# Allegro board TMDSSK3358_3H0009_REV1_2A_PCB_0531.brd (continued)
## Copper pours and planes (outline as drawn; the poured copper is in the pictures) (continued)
VBAT on BOTTOM: 116.71,26.8 117.47,27.56 117.47,32.51 117.86,32.89 122.17,32.89 122.55,32.51 122.55,27.94 117.86,23.24 117.86,21.46 116.08,19.69 107.7,19.69 106.55,20.83 106.55,22.48 107.67,23.6 107.67,24.65 109.82,26.8
VBAT on BOTTOM: 29.93,28.02 29.93,25.1 29.8,24.97 29.8,23.83 29.93,23.7 31.32,23.7 31.45,23.83 31.45,24.71 30.94,25.22 30.94,27.89 30.82,28.02
VBAT on BOTTOM: 120.34,46.36 123.7,46.36 123.83,46.23 123.83,44.7 123.63,44.51 122.62,44.51 122.39,44.29 122.39,43.33 122.24,43.18 120.35,43.18 120.03,43.51 120.03,46.05
VBAT on LYR4_PWR1: 87.9,0.94 87.9,4.87 87.62,5.15 61.13,5.15 60.97,5 60.97,1.21 61.46,0.73 87.69,0.73
VBAT on LY5_PWR2: 8.16,1.34 8.16,3.76 7.9,5.22 7.15,6.5 21.71,6.5 24.63,9.42 24.63,17.55 22.87,19.3 0.89,19.3 0.89,53.53 1.39,54.02 30.42,54.02 31.26,53.18 31.26,31.56 44.07,18.74 56.63,18.74 57.07,18.3 57.07,16.26 58.79,14.55 58.79,10.44 64.02,5.2 81.66,5.2 86.59,10.13 108.74,10.13 111.31,12.7 111.31,27.08 110.65,27.73 109.06,27.73 108.75,28.04 108.75,41.51 110.87,43.63 112.69,43.63 113.85,44.79 113.85,46.55 113.28,47.12 106.51,47.12 106.03,47.6 106.03,51.48 106.24,51.69 107.31,51.69 107.35,51.72 116.84,51.72 119.39,49.17 123.28,49.17 124.7,50.59 124.7,62.61 125.14,63.04 132.28,63.04 132.64,62.68 132.64,8.39 132.22,7.97 127.78,7.97 124.8,6.73 123.56,3.76 123.56,1.12 123.33,0.89 8.62,0.89
VBAT_WLAN on TOP: 20.28,32.97 20.28,36.91 20.91,36.91 21.04,37.03 21.04,38.43 20.94,38.52 20.94,39.22 19.95,40.21 19.64,40.21 19.13,39.7 19.13,36.52 18.37,35.76 18.37,33.22 18.62,32.97
VBAT_WLAN on BOTTOM: 19.3,40.51 19.3,38.73 20.07,37.97 24.64,37.97 25.27,38.61 25.27,40.51 25.02,40.77 19.56,40.77
VBAT_WLAN_OUT on BOTTOM: 19.64,45.03 19.5,45.03 19.5,43.4 19.77,43.13 19.77,41.73 20.02,41.48 24.97,41.48 25.1,41.61 25.1,43 23.45,44.65 20.02,44.65
VDD_1V8FT on TOP: 30.66,31.75 30.66,25.91 32.7,23.88 36,23.88 38.67,26.54 39.68,26.54 41.87,28.73 43.97,28.73 45.9,26.8 48.52,26.8 49.66,25.65 50.55,25.65 50.98,26.09 50.98,28.19 46.29,32.89 31.81,32.89
VDD_CORE on TOP: 104.22,41.18 103.46,41.18 102.84,40.55 102.84,39.19 104.01,38.02 106.43,38.02 106.76,38.35 108.39,38.35 108.59,38.56 108.59,39.65 108.44,39.8 107.55,39.8 106.91,40.44 106.91,41.99 106.51,42.39 104.68,42.39 104.37,42.09 104.37,41.33
VDD_CORE on TOP: 71.94,29.72 76.26,29.72 76.89,30.35 76.89,33.4 73.84,36.45 71.09,36.45 70.78,36.14 70.78,35.6 70.25,35.06 70.25,31.41
VDD_CORE on BOTTOM: 108.77,40 108.77,40.36 107.88,41.25 107.11,41.25 106.2,42.16 104.86,42.16 104.45,41.76 104.45,41.38 104.12,41.05 103.28,41.05 102.93,40.69 102.93,38.43 103.26,38.1 108.13,38.1 108.41,38.38 108.41,38.76 109.09,39.45 109.12,39.45 109.26,39.59 110.38,39.59 110.54,39.75 111.34,39.75 111.34,39.92 109.66,39.92 109.58,40
VDD_CORE on LYR4_PWR1: 64.33,32.43 64.33,39.59 69.82,45.08 91.62,45.08 93.36,43.35 107.07,43.35 108.13,42.29 108.13,38.09 108.02,37.97 74.1,37.97 73.59,37.47 73.59,36.05 74.16,35.48 74.69,35.48 75.35,34.82 75.35,34.26 76.71,32.9 76.71,31.95 76.51,31.75 65.01,31.75
VDD_FTREGIN on BOTTOM: 36.86,37.41 36.86,35.94 37.31,35.48 37.31,34.24 37.54,34.24 37.54,35.53 38.13,36.12 38.13,37.41
VDD_MPU on BOTTOM: 112.41,30.81 113.42,31.81 113.42,32.46 113.72,32.77 114.61,32.77 114.85,32.52 114.85,31.41 115.08,31.19 115.08,29.66 113.12,27.71 105.17,27.71 105.04,27.84 105.04,30.04 105.3,30.3 106.94,30.3 107.46,30.81
VDD_MPU_AM335X on TOP: 89.42,30.42 89.42,31.13 89.66,31.37 91.06,31.37 91.31,31.11 91.31,30.03 90.55,29.27 90.55,27.69 90.3,27.43 89.15,27.43 88.65,27.94 88.65,29.64
VDD_MPU_AM335X on BOTTOM: 106.86,33.53 103.44,33.53 103.14,33.23 103.14,32.08 100.72,29.66 100.72,28.52 101.49,27.76 104.41,27.76 104.66,28.01 104.66,29.66 104.41,29.92 104.41,30.81 104.66,31.06 106.81,31.06 107.12,31.37 107.12,33.27
VDD_MPU_AM335X on LYR4_PWR1: 87.69,27.78 105.25,27.78 108.13,30.67 108.13,37.19 107.98,37.34 74.33,37.34 74.1,37.11 74.1,36.1 74.33,35.86 74.84,35.86 75.73,34.97 75.73,34.46 77.09,33.1 77.09,32.11 77.62,31.57 83.91,31.57
VDDA_ADC on TOP (solid shape): outline of 156 points within 79.43,30.12 85.1,32.51
VDDL_PHY on BOTTOM: 92.1,41.17 91.55,41.17 91.32,40.94 88.9,40.94 88.87,40.97 88.87,41.5 89.03,41.66 89.03,42.88 88.77,43.13 88.77,45.4 88.5,45.67 88.25,45.67 87.94,45.97 87.94,47.88 88.7,48.64 92.13,48.64 92.23,48.54 92.23,46.71 92.23,46.71 90.65,45.14 90.65,44.07 91.59,43.13 91.77,43.13 92.24,42.66 92.24,41.31
VDDL_PHY2 on BOTTOM: 49.33,41.15 48.93,41.55 48.93,42.14 48.39,42.68 48.39,44.42 47.37,45.44 47.37,49.91 47.62,50.17 51.82,50.17 52.2,49.78 52.2,48.77 51.94,48.51 49.28,48.51 48.89,48.13 48.89,46.29 49.51,45.67 49.51,43.33 50.7,42.14 51.39,42.14 51.9,41.63 51.9,41.48 51.57,41.15
VDDS_DDR on BOTTOM: 126.36,34.04 119.92,34.04 119.83,34.13 119.83,34.36 120.05,34.59 120.31,34.59 120.64,34.92 120.64,35.2 120.82,35.38 121.81,35.38 122.44,36.01 122.44,37.38 122.1,37.72 121.88,37.72 121.62,37.97 121.62,38.93 120.64,39.92 120.64,39.92 120.41,40.15 119.04,40.15 118.89,40 118.45,40 118.02,40.43 118.02,40.56 118.48,40.56 118.91,40.99 120.84,40.99 122.08,39.75 127.25,39.75 127.63,39.37 127.63,37.34 127.13,36.83 127.13,34.8
VDDS_DDR on BOTTOM: 63.26,13.15 63.4,13.29 63.4,15.13 63.27,15.27 61.43,15.27 60.85,14.68 59.2,14.68 58.94,14.42 58.94,12.39 59.83,11.5 60.69,11.5 62.35,13.15
VDDS_DDR on LYR4_PWR1: 87.65,5.71 61.17,5.71 60.97,5.91 60.97,8.86 59.4,10.43 59.4,15.24 59.98,15.82 59.98,22.88 60.11,23.01 63.36,23.01 68.36,28.01 69.74,28.01 70.24,28.51 70.24,30.92 70.43,31.11 78.14,31.11 78.16,31.09 81.22,31.09 81.82,31.69 84.01,31.69 83.96,31.75 84.24,31.75 88.43,27.55 105.42,27.55 108.88,31.01 108.88,38.48 109.14,38.73 122.94,38.73 123.7,37.97 123.7,34.16 120.2,30.66 120.2,20.58 118.67,19.05 91.26,19.05 87.91,15.7 87.91,5.98
VDDS_DDR on LY5_PWR2: 61.51,15.21 61.74,15.44 61.74,19.38 67.91,25.55 76.65,25.55 78.32,27.22 78.32,27.91 78.42,28.01 82.66,28.01 88.45,22.23 93.68,22.23 93.99,21.92 93.99,11.68 93.08,10.77 86.36,10.77 81.33,5.74 67.25,5.74 67.2,5.69 63.59,5.69 59.35,9.93 59.35,14.75 59.81,15.21
VDDS_DDR3_AM335X on TOP: 74.99,28.57 74.86,28.7 74.23,28.7 74.1,28.57 72.14,28.57 72.12,28.6 72.12,29.13 72.04,29.21 71.56,29.21 71.51,29.26 71.51,29.51 71.53,29.54 72.42,29.54 72.55,29.41 73.79,29.41 73.84,29.46 75.7,29.46 75.83,29.34 76.86,29.34 77.07,29.54 77.07,29.9 77.11,29.94 77.11,29.95 77.4,29.95 77.45,29.9 77.45,28.6 77.45,28.6 77.45,26.9 77.34,26.8 75.44,26.8 74.99,27.25
VDDS_DDR3_AM335X on BOTTOM: 59.31,18.8 59.56,19.05 59.56,23.24 59.69,23.37 60.82,23.37 61.13,23.06 61.13,22.3 61.98,21.45 61.98,20.8 62.48,20.29 62.48,18.35 61.35,17.22 61.35,15.95 60.85,15.44 59.2,15.44 58.94,15.69 58.94,17.6 59.31,17.97
VDDS_DDR3_AM335X on LY5_PWR2: 58.5,15.57 60.95,15.57 61.1,15.72 61.1,19.5 67.53,25.93 76.46,25.93 77.95,27.42 77.95,29.11 77.83,29.23 64.88,29.23 64.72,29.07 64.72,27.28 64.43,26.99 64.43,26.15 63.52,25.24 62.68,25.24 57.72,20.28 57.72,16.34
VDDSHV1 on TOP (solid shape): outline of 842 points within 58.67,26.16 69.85,50.31
VDDSHV2 on TOP: 66.15,33.35 69.15,33.35 69.37,33.58 69.65,33.58 69.85,33.78 69.85,34.62 69.55,34.92 68.38,34.92 67.8,35.51 67.8,36.77 67.07,37.5 67.07,38.55 65.42,40.2 65.42,43.63 64.4,44.65 64.4,46.68 63.26,46.68 63.13,46.55 63.13,44.67 64.28,43.53 64.28,39.41 66.05,37.64 66.05,33.45
VDDSHV2 on BOTTOM: 66.17,44.6 66.17,43.23 65.81,42.87 64.06,42.87 63.75,43.18 63.75,45.36 64.42,46.02 65.94,46.02 66.05,45.91 66.05,44.72
VDDSHV3 on TOP: 70.99,43.43 69.98,42.42 69.98,37.87 70.24,37.61 70.24,35.57 69.85,35.18 68.76,35.18 68.15,35.79 68.15,36.59 68.97,37.41 68.97,38.93 68.72,39.19 68.72,41.85 68.58,41.85 68.58,42.8 69.15,43.36 69.15,47.45 69.95,48.26 70.69,48.26 70.99,47.96
VDDSHV4 on TOP: 75.56,41.38 75.56,39.39 74.17,37.99 74.17,36.83 74.42,36.58 75.56,36.58 75.69,36.7 75.69,36.34 76.83,37.48 76.83,37.54 77.74,38.44 77.74,39.7 77.1,40.33 77.1,40.46 78.25,41.6 78.88,41.6 80.02,42.74 80.02,46.68 80.79,47.44 80.79,47.64 80.76,47.67 80.76,49.63 79.77,50.62 77.23,50.62 76.98,50.36 76.98,49.73 78.25,48.46 78.25,43.1 76.19,43.1 75.91,42.83 75.91,41.73
VDDSHV4 on LY3_SIG1: 98.71,62.08 102.17,65.53 108.26,65.53 108.77,66.04 108.77,68.71 108.39,69.09 96.27,69.09 95.56,68.38 95.56,62.78 96.27,62.08
VDDSHV5 on TOP: 71.37,46.99 71.37,43.31 70.99,42.93 70.99,37.19 71.39,36.79 72.94,36.79 73.15,37.01 73.15,37.39 73.46,37.7 73.46,40.67 73.15,40.98 73.15,47.09 72.97,47.27 71.65,47.27
VDDSHV6 on TOP: 80.96,45.08 84.26,45.08 84.39,44.96 84.39,42.98 84.2,42.8 81.08,42.8 80.83,43.05 80.83,44.96
VDDSHV6 on BOTTOM: 32,44.83 32,43.69 32.38,43.31 48.06,43.31 48.19,43.43 48.19,44.07 48.06,44.2 47.56,44.2 46.54,45.21 32.38,45.21
VDDSHV6 on LYR4_PWR1: 66.89,26.63 67.61,27.35 67.61,27.53 67.82,27.75 68,27.75 68.24,27.99 68.24,28.13 68.46,28.35 69.39,28.35 69.72,28.68 69.74,28.66 69.74,30.97 69.6,31.11 65.95,31.11 65.93,31.1 64.75,31.1 59.83,26.18 59.83,23.64 60.16,23.31 63.59,23.31 66.89,26.61
VDDSHV6 on LY5_PWR2: 44.49,19.17 31.66,32 31.66,53.28 30.39,54.55 1.37,54.55 0.89,55.04 0.89,62.68 1.25,63.04 3.95,63.04 6.93,64.28 8.16,67.25 8.16,69 9.28,70.12 34.51,70.12 34.52,70.13 45.39,70.13 45.59,69.92 45.59,48.92 47.55,46.96 47.55,38.91 48.44,38.02 51.36,38.02 52.63,39.29 52.63,52.35 59.97,59.69 97.51,59.69 97.92,59.28 97.92,53.47 99.72,51.66 105.19,51.66 105.41,51.44 105.41,46.76 104.1,45.44 104.1,45.41 101.77,43.08 101.77,33.75 103.8,31.72 103.8,30.51 101.7,28.42 91.38,28.42 87.01,32.79 87.01,35.4 85.69,36.72 84.62,36.72 81.98,34.08 77.76,34.08 75.5,36.35 75.5,37.21 75.75,37.47 76.26,37.47 77.15,36.58 77.67,36.58 77.89,36.8 77.89,37.74 78.25,38.1 82.1,38.1 82.11,38.11 84.25,38.11 86.26,40.13 86.26,41.35 85.07,42.55 68.51,42.55 64.32,38.35 64.32,27.29 57.54,20.52 57.54,19.99 56.73,19.17
VDDSHV6 on LY6_SIG2: 75.73,36.75 75.85,36.64 76.05,36.64 76.33,36.36 76.33,34.48 77.23,33.57 77.51,33.57 77.74,33.8 77.74,36.37 76.87,37.23 75.81,37.23 75.73,37.16
(no net) on TOP: 79.53,31.78 79.43,31.88 79.43,32.39 79.56,32.51 83.02,32.51 83.33,32.2 84.62,32.2 85.1,31.72 85.1,30.28 84.94,30.12 82.35,30.12 80.7,31.78
(no net) on TOP: 23.58,49.38 22.29,49.38 22.05,49.61 22.05,50.88 22.31,51.13 25.48,51.13 25.86,50.75 25.86,49.86 25.61,49.61 23.81,49.61
(no net) on TOP: 65.02,32.77 69.3,32.77 69.6,32.51 69.85,32.26 69.85,31.29 69.55,30.99 65.34,30.99 63.81,29.46 63.15,28.8 61.31,28.8 60.71,28.19 60.71,26.29 60.58,26.16 58.76,26.16 58.67,26.25 58.67,29.84 58.8,29.97 60.89,29.97 63.08,32.17 63.08,35.02 63.12,35.05 63.12,35.38 62.2,36.3 62.2,36.65 61.74,37.12 61.74,38.41 62.2,38.88 62.2,42.66 61.48,43.38 61.48,46.83 62.78,48.12 62.78,48.87 64.22,50.31 67.4,50.31 67.65,50.06 67.65,49.75 66.82,48.92 65.82,48.92 64.5,47.6 63.41,47.6 62.75,46.93 62.75,44.27 63.88,43.14 63.88,38.99 63.5,38.61 63.5,37.34 63.88,36.96 63.88,36.45 64.39,35.94 64.39,34.8 63.88,34.29 63.88,33.91
(no net) on BOTTOM: 27.32,50.55 25.74,48.97 22.89,48.97 22.85,49.02 22.85,49.22 23.47,49.84 23.67,49.84 25.06,51.23 25.06,52.04 25.43,52.4 28.08,52.4 28.23,52.25 28.23,50.65 28.12,50.55
(no net) on BOTTOM: 27.3,46.39 25.23,48.46 22.92,48.46 22.82,48.37 22.76,48.37 22.76,47.75 22.92,47.6 23.68,47.6 25.46,45.82 25.46,44.71 25.64,44.53 28.04,44.53 28.2,44.68 28.2,46.26 28.07,46.39
(no net) on BOTTOM: 22.05,51.84 22.23,52.02 23.7,52.02 23.83,51.89 23.83,50.59 23.46,50.21 23,50.21 22.54,49.75 22.54,49.5 22.47,49.42 21.88,49.42 21.88,49.78 22.05,49.95
BKLT_L on BOTTOM: 26.37,41.86 26.37,40.08 25.99,39.7 25.99,35.51 26.5,35 28.02,35 28.28,35.26 28.28,41.48 27.64,42.11 26.63,42.11
BKLT_SW on BOTTOM: 29.29,41.99 29.29,35.18 29.47,35 30.57,35 31.83,36.26 31.83,39.83 30.56,41.1 30.56,42.11 30.31,42.37 29.67,42.37
CHASSIS_ETH1 on TOP: 78.1,58.04 89.79,58.04 91.57,59.82 93.85,59.82 94.11,59.56 94.11,55.75 93.54,55.18 92.01,55.18 90.93,56.26 79.5,56.26 79.44,56.2 78.68,56.2 77.85,55.37 75.31,55.37 74.68,56.01 74.68,58.93 75.31,59.56 76.58,59.56
CHASSIS_ETH2 on TOP: 53.04,58.17 53.04,55.22 54.08,54.18 55.8,54.18 56.87,55.25 70.69,55.25 70.97,55.52 71.81,55.52 73.25,56.97 73.25,58.04 72.92,58.37 72.14,58.37 71.55,58.95 70.23,58.95 68.99,57.71 67.18,57.71 67.23,57.76 56.21,57.76 54.89,59.08 53.95,59.08
CHASSIS_SD on BOTTOM: 100.76,54.89 100.13,55.52 100.13,56.08 99.23,56.98 99.23,57.68 99.05,57.86 98.41,57.86 98.34,57.78 98.34,57.05 98.08,56.79 97.05,56.79 96.44,57.4 96.44,60.76 97.41,61.72 97.41,62.89 97.18,63.12 96.34,63.12 94.01,65.46 94.01,69.65 94.73,70.37 98.53,70.37 98.53,69.14 98.25,68.86 96.44,68.86 96.09,68.5 96.09,66.45 96.9,65.63 98.25,65.63 98.97,64.91 99.23,64.91 99.82,64.31 110.54,64.31 113.03,66.8 113.03,68.53 112.67,68.88 111.46,68.88 111.4,68.94 111.4,70.2 111.58,70.37 115.3,70.37 115.95,69.72 115.95,66.98 115.34,66.37 115.34,66.32 115.14,66.12 114.53,66.12 114.35,65.94 114.35,65.46 113.49,64.59 113.49,59.33 110.57,56.41 110.59,56.41 109.07,54.89
CHASSIS_USB0 on LY3_SIG1: 49.87,69.42 49.87,66.75 48.52,65.41 37.5,65.41 35.9,67.01 35.9,69.55 36.28,69.93 49.36,69.93
CHASSIS_USB1 on TOP: 28.91,65.23 31.71,65.23 33.36,63.58 33.36,60.15 31.96,58.75 29.29,58.75 27.9,60.15 27.9,64.21
CHASSIS_USB1 on LY6_SIG2: 27.9,59.26 19.79,59.26 18.47,57.94 15.5,57.94 14.28,59.16 14.28,66.62 15.98,68.33 29.7,68.33 33.28,64.74 33.28,58.72 32.37,57.81 29.34,57.81
LED+ on TOP: 31.37,34.79 29.27,34.79 28.15,35.92 28.15,37.29 28.55,37.69 29.48,37.69 30.33,38.54 30.33,40.39 30.49,40.56 31.69,40.56 31.81,40.43 31.81,38.78 30.54,37.51 30.54,35.96 30.65,35.86 30.9,35.86 31.37,35.39
LED- on TOP: 31.31,34.49 31.46,34.34 31.46,33.14 31.34,33.02 28.84,33.02 27.8,34.06 26.68,34.06 25.99,34.75 25.99,38.94 26.11,39.07 27.06,39.07 27.06,37.74 27.77,37.03 27.77,35.77 29.05,34.49
PWR_SMPS1 on BOTTOM: 112.73,31.8 112.53,31.6 107.88,31.6 107.68,31.8 107.68,33.12 108.49,33.93 111.07,33.93 111.61,34.48 111.94,34.81 111.94,35.41 112.04,35.51 112.52,35.51 112.59,35.44 112.59,33.5 112.73,33.36
PWR_SMPS2 on BOTTOM: 108.34,37.31 104.02,37.31 103.6,36.89 103.6,35.27 104.2,34.67 107.75,34.67 109.15,36.07 109.15,37.27 109.73,37.85 109.73,38.61 109.93,38.81 110.52,38.81 110.69,38.99 111.38,38.99 111.4,39.01 111.32,39.1 110.68,39.1 110.46,39.32 109.32,39.32 108.88,38.87 108.88,37.85
PWR_SWIO on BOTTOM: 116.59,41.2 116.59,40.94 117.46,40.97 118.34,40.97 118.72,41.35 121.14,41.35 122.22,40.26 127.63,40.26 127.79,40.41 127.79,42.44 127.46,42.77 118.93,42.77 118.01,41.86 118.01,41.63 117.58,41.2
USB0_VBUS on LY6_SIG2: 67.31,39.67 67.31,37.67 67.61,37.36 69.6,37.36 69.77,37.54 69.77,38.02 69.62,38.18 69.37,38.18 69.22,38.33 69.22,38.91 68.38,39.75 67.39,39.75
VADDL_PHY on BOTTOM: 87.2,43.36 87.2,41.68 87.33,41.55 88.52,41.55 88.7,41.73 88.7,42.06 88.44,42.32 88.44,43.38 88.39,43.43 87.27,43.43
VADDL_PHY on LY3_SIG1: 96.49,45.14 96.49,44.09 98.78,41.81 98.78,39.47 99.07,39.18 99.94,39.18 100.33,39.57 100.33,42.42 97.31,45.44 96.8,45.44
VADDL_PHY on LY6_SIG2: 87.25,42.34 87.25,41.71 87.5,41.45 90.07,41.45 91.06,40.46 92.23,40.46 92.48,40.72 92.48,41.53 91.47,42.55 87.45,42.55
VADDL_PHY2 on TOP: 55.5,45.47 55.5,43.18 55.88,42.8 58.17,42.8 58.42,42.55 58.42,41.53 58.93,41.02 58.93,40.39 58.55,40 58.55,39.12 58.67,38.99 59.44,38.99 59.96,39.51 59.96,40.98 60.58,41.61 60.58,44.32 59.18,45.72 58.49,45.72 58.31,45.54 57.82,45.54 57.64,45.72 55.75,45.72
VADDL_PHY2 on BOTTOM: 44.83,49.63 44.83,48.84 45.06,48.62 45.59,48.62 45.8,48.82 46.76,48.82 46.89,48.95 46.89,49.78 46.79,49.89 45.08,49.89
VADDL_PHY2 on LY6_SIG2: 44.59,49.6 44.59,48.84 44.84,48.59 45.73,48.59 46.11,48.97 46.11,49.73 45.73,50.11 45.1,50.11
VAUX2 on TOP: 82.18,48.71 82.18,47.7 82.56,47.32 82.56,45.41 84.21,45.41 84.47,45.66 84.47,46.81 83.83,47.44 83.83,48.71 83.45,49.09 82.56,49.09
VAUX2 on TOP: 106.06,43.94 106.06,43.43 106.44,43.05 107.28,43.05 107.43,43.2 107.43,44.06 107.22,44.27 106.39,44.27
VAUX2 on BOTTOM: 106.21,43.35 106.29,43.28 106.74,43.28 106.91,43.11 107.29,43.11 107.46,43.28 108.42,43.28 110.33,41.37 111.39,41.37 111.42,41.4 111.42,41.85 111.09,42.19 110.17,42.19 108.08,44.27 106.83,44.27 106.21,43.66
VAUX33 on TOP: 90.42,4.19 90.42,4.57 90.55,4.57 91.56,5.58 94.8,5.58 97.8,8.58 97.8,11.76 98.11,12.06 101.94,12.06 102.38,11.63 102.38,6.68 98.95,3.25 93.27,3.25 92.96,3.56 92.96,4.19 92.84,4.32 91.44,4.32 91.31,4.19
VAUX33 on LY3_SIG1: 107.82,25.65 108.71,25.65 109.22,26.16 109.22,33.47 108.6,34.09 108.6,37.73 113.79,42.93 113.79,46.6 113.26,47.14 109.25,47.14 108.84,46.73 108.84,40.89 106.57,38.62 106.57,33.43 106.93,33.07 106.93,26.54
VAUX33 on LY5_PWR2: 110.67,26.82 110.67,13.11 108.41,10.84 95.47,10.84 94.63,11.68 94.63,21.97 94.89,22.23 103.26,22.23 107.57,26.54 107.57,26.54 108.2,27.18 110.32,27.18
VAUX33 on LY6_SIG2: 109.19,49.83 109.19,44.32 109.83,43.69 111.38,43.69 112.27,44.58 112.27,46.06 112.97,46.76 114.49,46.76 115.91,45.34 118.72,45.34 120.07,46.69 120.07,49.88 119.5,50.45 119.5,50.52 109.88,50.52
VCOM_BAT on TOP: 25.48,23.06 25.48,25.98 25.86,26.37 28.02,26.37 28.4,25.98 28.4,24.97 28.78,24.59 28.78,23.32 28.53,23.06
VCOM_BAT on BOTTOM: 27.39,28.14 27.39,26.24 27.13,25.98 27.13,20.52 27.77,19.89 32.47,19.89 32.85,20.27 32.85,22.05 32.34,22.56 29.93,22.56 29.17,23.32 29.17,25.1 28.4,25.86 28.4,28.02 28.28,28.14
VCOM_BAT on BOTTOM: 19.13,44.27 19.13,44.91 19.01,45.03 15.58,45.03 15.45,44.91 15.45,44.53 15.83,44.15 19.01,44.15
VCOM_BAT on LYR4_PWR1: 27.49,46.99 31.31,43.17 31.31,27.55 31.28,27.58 31.28,22.73 30.73,22.17 25.92,22.17 24.09,24.01 24.09,36.27 20.28,40.08 2.43,40.08 2.42,40.09 1.3,40.09 0.89,40.5 0.89,46.64 1.24,46.99
VDAC on TOP: 84.85,41.5 87.12,41.5 87.27,41.35 87.27,40.08 87.17,39.98 85.32,39.98 84.45,40.84 84.31,40.84 83.76,41.4 83.76,41.58 84.04,41.85 84.49,41.85
VDAC on BOTTOM: 119.65,38.17 120,38.53 120,38.88 120.26,39.14 120.56,39.14 120.84,38.86 120.84,37.87 120.49,37.51 120.49,36.95 120.31,36.77 119.32,36.77 118.35,37.74 117.64,37.74 117.64,38.07 117.74,38.17
VDAC on LY5_PWR2: 64.95,38.1 68.76,41.91 84.84,41.91 85.6,41.15 85.6,40.34 84,38.73 78.25,38.73 77.36,37.85 75.85,37.85 74.96,38.73 73.72,38.73 73.21,38.23 73.21,36.32 72.96,36.07 71.69,36.07 71.62,36.13 68.83,36.13 68.76,36.2 68.64,36.2 67.62,35.18 67.62,32.89 68.13,32.39 69.27,32.39 69.4,32.51 75.98,32.51 76.16,32.33 76.16,31.95 76.49,31.62 77.04,31.62 77.3,31.37 77.3,29.93 76.96,29.59 65.49,29.59 64.95,30.13
VDAC on LY6_SIG2: 86.59,38.05 89,38.05 89.31,37.74 94.23,37.74 96.49,35.48 104.77,35.48 108.22,38.93 112.03,38.93 114.41,36.55 120.32,36.55 121.16,37.39 121.16,38.74 119.06,40.84 115.33,40.84 114.44,41.73 105.3,41.73 101.31,37.74 98.5,37.74 96.37,39.88 89.94,39.88 88.62,41.2 86.92,41.2 86.23,41.88 83.94,41.88 83.81,41.75 83.81,40.83
VDIG1 on TOP: 56.92,28.04 56.54,27.66 56.53,24.33 57.04,23.82 58.05,23.82 58.45,24.13 58.45,27.89 58.17,28.16 57.04,28.16 56.92,28.05
VDIG1 on BOTTOM: 118.2,1.52 118.2,2.33 117.97,2.56 115.18,2.56 115.16,2.55 114.96,2.55 114.52,2.1 114.52,1.24 114.64,1.11 117.79,1.11
VDIG1 on BOTTOM: 113.88,43.33 114.19,43.02 114.42,43.02 114.75,43.35 114.75,44.19 113.93,45 113.93,46.12 113.75,46.3 113.3,46.3 113.04,46.05 113.04,45.59 112.92,45.46 112.46,45.46 112.33,45.33 112.33,44.9 112.41,44.83 113.32,44.83 113.88,44.27
VDIG1 on LY6_SIG2: 114.99,2.31 114.99,1.58 115.23,1.34 118.1,1.34 118.47,1.71 118.47,2.34 118.01,2.79 115.47,2.79
VDIG1 on LY6_SIG2: 112.92,45.87 112.92,44.75 113.09,44.57 114.34,44.57 114.34,45.87 114.14,46.07 113.12,46.07
VDIG2 on LY5_PWR2: 74.61,38.35 73.97,38.35 73.59,37.97 73.59,35.94 73.34,35.69 68.76,35.69 68,34.92 68,33.15 68.37,32.78 69.04,32.78 69.16,32.89 76.08,32.89 76.51,32.46 76.51,32.1 76.68,31.93 76.92,31.93 77.11,31.74 77.62,31.74 77.77,31.58 77.77,29.63 77.89,29.51 78.16,29.51 78.55,29.12 78.55,28.7 78.67,28.57 83,28.57 88.71,22.86 103,22.86 108.14,28 108.14,41.92 110.44,44.22 112.33,44.22 113.21,45.1 113.21,46.23 112.84,46.61 106.18,46.61 104.71,45.14 104.71,45.13 101.92,42.34 101.92,34.26 104.71,31.47 104.71,30.58 102.06,27.94 91.27,27.94 86.54,32.66 86.54,35.26 85.6,36.2 84.77,36.2 82.23,33.66 77.58,33.66 74.99,36.25 74.99,37.97
VETH2_AVDD_3_3 on BOTTOM: 59.63,46.23 63.12,46.23 63.37,45.97 63.37,44.7 63.07,44.4 61.37,44.4 61.01,44.04 61.01,41.2 60.45,40.64 60.07,40.64 59.94,40.77 59.94,41.15 60.2,41.4 60.2,42.67 60.33,42.8 60.33,43.94 60.2,44.07 60.2,44.92 59.45,45.66 59.45,46.05
VETH2_LX on BOTTOM: 50.17,48.13 52.58,48.13 53.44,47.27 53.44,45.62 53.97,45.08 53.97,44.07 53.85,43.94 53.09,43.94 51.94,45.08 51.94,46.36 51.18,47.12 50.29,47.12 50.04,47.37 50.04,48.01
VETH_AVDD_3_3 on BOTTOM: 100.96,41.78 101.73,42.55 101.73,45.59 101.98,45.85 102.87,45.85 103.12,45.59 103.12,42.29 103,42.16 102.87,42.16 102.49,41.78 102.49,41.27 102.23,41.02 101.09,41.02 100.96,41.15
VETH_LX on BOTTOM: 92.84,48.51 92.84,46.74 93.09,46.48 93.38,46.48 94.02,45.84 94.02,43.94 94.45,43.51 94.65,43.51 95.09,43.94 95.09,46.9 94.68,47.31 94.68,47.94 93.98,48.64 92.96,48.64
VMMC on TOP: 32.94,11.84 32.94,8.76 33.07,8.64 33.73,8.64 34.06,8.97 34.06,11.84 33.9,12 33.11,12
VMMC on TOP: 106.87,51.53 106.87,45.27 106.98,45.16 107.49,45.16 107.87,44.78 107.89,44.78 107.91,44.76 108.25,44.76 108.37,44.89 108.37,47.93 107.81,48.49 107.81,50.44 108.33,50.96 109.54,50.96 109.54,52.43 109.44,52.53 107.88,52.53
VMMC on TOP: 67.7,37.28 67.2,37.79 67.2,38.55 65.93,39.82 65.93,43.89 64.78,45.03 64.78,47.06 66.31,48.59 67.3,48.59 68.59,49.88 75.86,49.88 77.61,48.13 77.61,45.46 73.75,45.46 73.67,45.54 73.67,47.9 73.06,48.51 69.74,48.51 68.8,47.57 68.8,47.14 68.78,47.13 68.85,47.06 68.85,45.54 68.72,45.41 67.07,45.41 66.82,45.16 66.82,41.85 66.56,41.6 66.56,40.58 66.82,40.33 67.32,40.33 68.72,38.93 68.72,38.27 68.4,37.95 68.4,37.67 68.51,37.56 68.51,37.49 68.31,37.28
VMMC on TOP: 85.94,20.39 85.94,20.14 86.14,19.93 87.19,19.93 87.52,20.26 87.52,20.85 87.29,21.08 86.63,21.08
VMMC on BOTTOM: 107.15,45.53 107.15,45.02 107.48,44.7 108.83,44.7 108.84,44.69 109.18,45.03 109.18,45.33 109.08,45.44 108.24,45.44 107.94,45.74 107.37,45.74
VMMC on BOTTOM: 30.48,29.18 31.22,28.45 31.22,26.52 31.32,26.42 32.16,26.42 32.26,26.52 32.26,28.63 31.24,29.64 30.61,29.64 30.48,29.51
VMMC on LY3_SIG1: 85.47,18.12 85.47,24.03 83.48,26.02 83.12,26.02 79.01,30.14 78.83,30.32 78.63,30.32 76.9,32.05 76.9,32.81 76.51,33.2 70.97,33.2 70.18,33.99 70.18,38.13 70.31,38.25 70.92,38.25 71.4,37.77 71.4,37.39 73.38,35.41 75.11,35.41 75.18,35.48 77.65,35.48 78.18,34.95 78.18,33.93 78.59,33.53 78.74,33.53 80.16,32.11 80.16,30.48 86.51,24.13 86.51,23.75 88.6,21.67 88.6,18.08 88.62,18.06 87.9,17.34 86.25,17.34
VMMC on LYR4_PWR1: 68.21,36.77 68.21,38.04 68.59,38.43 70.37,38.43 70.63,38.17 70.63,36.65 70.37,36.39 68.59,36.39
VPLL on BOTTOM: 116.65,37.13 117.97,37.13 118.58,36.52 120.18,36.52 120.36,36.34 120.36,35.23 119.85,34.72 119.5,34.72 118.5,35.71 117.06,35.71 116.6,36.17 116.6,37.08
VPWRIN_JCK on BOTTOM: 120.74,19.01 120.74,16.67 121.03,16.38 123.7,16.38 124.71,17.4 129.54,17.4 129.79,17.65 129.79,20.83 129.54,21.08 125.73,21.08 124.59,19.94 121.67,19.94
VPWRIN_PREFUSE on BOTTOM: 124.08,33.15 124.08,24.26 124.97,23.37 129.41,23.37 129.92,23.88 129.92,28.83 129.16,29.59 129.16,33.27 128.96,33.47 124.4,33.47
VREFP_ADC on TOP: 80.05,34.31 80.05,32.99 80.33,32.71 81.52,32.71 81.78,32.96 81.78,34.36 81.62,34.51 80.25,34.51
VRTC on TOP: 118.87,52.58 118.87,49.53 119.38,49.02 122.68,49.02 123.06,49.4 123.06,50.55 122.68,50.93 122.81,50.93 121.03,52.7 119,52.7
VRTC on BOTTOM: 121.28,48.89 121.41,49.02 121.41,51.94 121.16,52.2 117.22,52.2 115.32,54.1 114.17,54.1 113.41,53.34 113.41,50.99 113.37,50.95 112.13,50.95 112.08,51 112.08,52.7 112,52.78 111.6,52.78 111.24,53.13 111.24,53.74 111.04,53.95 110.61,53.95 109.94,53.28 109.94,50.14 110.45,49.63 112.9,49.63 112.9,48.39 113.16,48.13 115.95,48.13 116.71,48.89
VRTC on LY3_SIG1: 109.28,35.38 109.28,34.9 109.54,34.64 112.05,34.64 117.77,40.36 117.77,47.11 117.97,47.11 118.54,46.54 119.56,46.54 119.98,46.96 119.98,48.94 121.17,50.14 121.17,52.04 120.61,52.6 119.67,52.6 118.19,54.08 114.91,54.08 114.48,53.65 114.48,50.94 114.9,50.52 114.9,40.31 113.42,38.83 112.74,38.83
VRTC on LY5_PWR2: 48.17,47.21 46.23,49.15 46.23,69.92 46.24,69.92 46.45,70.13 98.98,70.13 99.59,69.52 110.87,69.52 111.48,70.13 122.98,70.13 123.57,69.54 123.57,62.92 124.08,62.42 124.08,50.8 123.06,49.78 119.64,49.78 117.1,52.32 99.96,52.32 98.54,53.74 98.54,59.58 97.78,60.35 59.75,60.35 51.94,52.53 51.94,39.5 51.05,38.61 48.77,38.61 48.17,39.2
VRTC_PMIC on TOP: 119.89,48.51 119.89,47.24 120.14,46.99 122.81,46.99 123.19,47.37 123.19,48.39 122.94,48.64 120.02,48.64
VRTC_PMIC on LY3_SIG1: 117.98,33.66 123.83,39.5 123.83,47.99 123.03,48.79 120.84,48.79 120.61,48.56 120.61,46.65 121.28,45.97 121.28,42.16 114.43,35.31 114.43,33.91 114.68,33.66
VTT_DDR on TOP: 83.69,1.4 83.69,3.04 83.68,3.04 83.43,3.3 83.15,3.3 83.12,3.32 83.12,5.27 83.79,5.94 83.79,15.65 83.44,16 83.44,17.34 83.45,17.34 83.71,17.6 84.93,17.6 85.04,17.48 85.04,15.85 85.69,15.2 85.69,15.16 85.99,14.85 87.3,14.85 87.5,14.65 87.5,11.81 87.48,11.79 87.48,10.86 85.21,8.58 85.21,6.14 84.82,5.76 84.82,3.96 85.18,3.6 86.56,3.6 86.66,3.5 86.66,3.28 86.23,2.84 86.74,2.34 86.74,2.16 86.11,2.16 85.85,1.9 85.85,1.84 85.34,1.33 83.76,1.33
VTT_DDR on BOTTOM: 87.26,14.8 87.14,14.93 85.99,14.93 85.41,14.35 85.41,13.61 85.74,13.28 85.74,8.83 85.99,8.58 87.14,8.58 87.39,8.83 87.39,12.52 87.26,12.64
VUSB_VBUS1 on BOTTOM: 68.5,46.79 68.5,48.54 67.97,49.07 67.97,53.87 69.37,55.27 69.52,55.27 70.08,54.71 70.08,50.62 69.67,50.22 69.67,49.3 70.03,48.95 70.03,46.74 69.93,46.63 68.73,46.63 68.58,46.79
VUSB_VBUS1 on BOTTOM: 21.22,59.39 18.88,59.39 17.48,57.99 16.08,57.99 14.94,56.85 14.94,53.16 15.07,53.04 17.99,53.04 19.01,54.05 20.36,54.05 21.13,54.81 22.52,54.81 22.77,55.06 23.1,55.06 23.18,55.14 23.18,55.29 21.78,56.69 21.78,58.82
VUSB_VBUS1 on LY3_SIG1: 19.25,60.2 19.25,56.16 20.19,55.22 27.56,55.22 32.97,60.63 51.18,60.63 54.15,63.6 56.49,63.6 59.11,60.99 59.11,59.23 62.84,55.5 68.33,55.5 68.61,55.22 68.61,53.47 69.32,52.76 69.88,52.76 70.43,53.31 70.43,55.37 58.88,66.93 51.89,66.93 48.92,63.96 23.01,63.96
N21904036 on BOTTOM (solid shape): 28.23,52.25 28.23,50.65 28.12,50.55 27.32,50.55 25.74,48.97 24.5,48.97 24.31,49.09 24.08,49.08 24.08,49.07 22.85,49.07 22.85,49.22 23.47,49.84 23.67,49.84 25.07,51.24 25.09,51.24 25.48,51.56 25.22,51.99 25.15,52.06 25.18,52.15 25.43,52.4 28.08,52.4
N21904046 on BOTTOM (solid shape): 27.3,46.39 28.07,46.39 28.2,46.26 28.2,44.68 28.04,44.53 25.64,44.53 25.46,44.71 25.46,45.82 23.68,47.6 22.92,47.6 22.76,47.75 22.76,48.36 24.08,48.36 24.08,48.36 24.31,48.35 24.5,48.46 25.23,48.46
N21930375 on BOTTOM: 13.67,22.43 15.2,22.43 15.2,20.78 13.8,20.78 13.54,20.52 12.95,20.52 12.5,20.98 12.5,22.07 12.98,22.56 13.54,22.56
N21930375 on BOTTOM: 26.63,19.13 33.1,19.13 33.36,18.87 33.36,16.59 33.1,16.33 26.75,16.33 26.5,16.59 26.5,19
N21930375 on LY3_SIG1: 12.99,19.93 12.99,22.77 13.67,23.44 23.96,23.44 27.39,20.02 27.39,16.85 26.87,16.33 25.74,16.33 23.45,18.62 14.31,18.62
N21930388 on BOTTOM: 11.94,33.91 11.94,42.27 13.33,43.66 15.42,43.66 15.49,43.59 15.49,38.79 15.01,38.79 14.45,38.23 14.45,37.08 14.17,36.8 14.17,33.55 13.59,32.97 12.88,32.97
N23838237 on TOP: 113.84,52.73 113.84,50.83 113.89,50.77 115.95,50.77 116.23,51.05 116.23,52.63 115.98,52.88 114,52.88
N27067217 on BOTTOM: 108.71,16 108.71,14.86 112.01,11.56 114.17,11.56 115.95,13.34 115.95,14.48 118.14,16.66 119.78,16.66 120.08,16.96 120.08,18.89 119.8,19.18 116.71,19.18 116.09,18.55 111.26,18.55
N27225472 on BOTTOM: 121.79,50.17 121.79,49.02 122.17,48.64 122.17,47.37 122.36,47.19 123.39,47.19 123.57,47.37 123.57,50.29 123.44,50.42 122.05,50.42

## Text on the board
BOTTOM: 3H0009 | LAYER 8 - SECONDARY SIDE | 8
Ref Des/Assembly Bottom: BOARD NO. 3H0009 | ASSEMBLY BOTTOM | 1.2 A | REV | DESCRIPTION | 05-31-12 | TEXAS INSTRUMENTS | DATE | TMDSSK3358 | CUSTOMER NAME | 2 | OF | BOARD NAME | SH
Board Geometry/Soldermask Bottom: SOLDERMASK BOTTOM
Ref Des/Silkscreen Bottom: REV 1.2A | SN#:_________________ | ARM MPU | TMDSSK3358 | ASSY PN 4P0019 | MICROSD | WARMRST | EXTINT | USB1 | DGND | GND | I2C | BOOT CONFIG | V1_8D | USB0 | B | HSET | _AM335X | VDDS_DDR | VDDSHV6 | VDDL_PHY | VDD_MPU | ZIGBEE | JTAG | V3_3D | PWRON | VDDL_PHY2 | VDDSHV2 | VDDSHV3 | GIGETH2 | GIGETH1 | VDDSHV4 | VDD_CORE | PWRIN | SLOW BLOW | 4A | 125VAC, | 125VDC
User.Comments: sdf | Green indicates power/gnd routing | 2 | 1
TOP: LAYER1 - PRIMARY SIDE | 1 | 8
Ref Des/Assembly Top: U5 | U9 | ASSEMBLY TOP | 1 | 2
Board Geometry/Soldermask Top: SOLDERMASK TOP
Ref Des/Silkscreen Top: USER LEDS | BOOT CONFIG | LCD CONN | CAP. TOUCH | VDDSHV5 | A | B | USER KEYS | PWR ON | 1 | 2
PAGE_OUTLINE: UNLESS OTHERWISE SPECIFIED | DIMENSIONS ARE IN INCH | TOLERANCES ON; | 2 PL DECIMALS + | 3 PL DECIMALS + | ANGLES + | FRACTIONS + | LAYOUT BY | REVIEWED BY | APPROVED BY | SIGNATURES | 1.1 A | 1.2 A | 1.0 A | REV | LnT | 05-31-12 | DATE | INITIAL RELEASE | BETA RELEASE | BETA2 RELEASE | DESCRIPTION | SCALE | SIZE | 1:1 | TEXAS INSTRUMENTS | TMDSSK3358- 1.2A | 04-02-12 | 02-03-12 | APPROVED
BODY_CENTER: J6 | J4 | J3 | J1
DISPLAY_BOTTOM: PASTEMASK TOP | 1 | 2
User.6: PASTEMASK BOTTOM | 2
User.7: CENTER LINE | LCD FLEX CABLE
User.10: LAYER 2 - GND PLANE 1 | 2 | 8
User.11: LAYER 3 - SINGAL 1 | 3 | 8
User.12: LAYER 4 - POWER PLANE 1 | 4 | 8
User.13: LAYER 5 - POWER PLANE 2 | 5 | 8
User.14: LAYER 6 - SIGNAL 2 | 6 | 8
User.15: LAYER 7 - GND PLANE 2 | 7 | 8
User.18: 2.000\P(2 PLCS.) | 2.500\P(2 PLCS.) | 3.250 | 0.760 | 0.110
User.19: 4.655 | 4.875 (2 PLCS.) | 5.625 | 2.280 | R0.125\P(4 PLCS.) | 2.500\P(2 PLCS.)
User.21: TM | YOUR PERFECT FIT | JOB NO: | DRWN BY | CUSTOMER: | TITLE: | APP. BY | PRODUCT: | REV | DESCRIPTION | BY | CHK | DATE | SCALE: | DATE: | C | L | dia 0.090\P(4 PLCS.) | 0.105 WALL THK.\P(TYP.) | 0.750\P(2 PLCS.) | dia 0.188\P(4 PLCS.) | 6.750 | 6.130 | 4.375 (2 PLCS.) | 4.875 (2 PLCS.) | 5.625 | 2.000\P(2 PLCS.) | 0.250\P(4 PLCS.) | 2.500\P(2 PLCS.) | 3.250 | 0.760 | 0.105\P(2 PLCS.) | 0.110 | POLYCASE
User.24: C | L | 2.280 | 0.750\P(2 PLCS.) | 6.750 | 6.130 | 4.655 | 4.375 (2 PLCS.) | 4.875 (2 PLCS.) | 5.625 | 0.250\P(4 PLCS.) | 2.000\P(2 PLCS.) | 2.500\P(2 PLCS.) | 3.250 | 1.147 | 0.926
User.25: TM | YOUR PERFECT FIT | THIS DRAWING AND THE INFORMATION CONTAINED | ARE THE PROPERTY OF POLYCASE AND IT IS NOT | TO BE REPRODUCED, COPIED OR USED IN ANY | WAY DETRIMENTAL TO THE INTEREST OF POLYCASE | JOB NO: | DRWN BY | CUSTOMER: | TITLE: | APP. BY | PRODUCT: | REV | DESCRIPTION | DATE | TOLERANCES UNLESS | OTHERWISE SPECIFIED | 1305 CHESTER IND. PARKWAY | AVON, OHIO 44011-1083 U.S.A. | PH#: 1-800-248-1233, 440-934-0444 | FAX#: 440-934-0088 | SCALE: | DATE: | C | L | dia 0.188 O.D.\P%%C0.090 I.D.\P(4 PLCS.) | 0.750\P(2 PLCS.) | 5.628 | 6.750 | 6.130 | 4.375 (2 PLCS.) | 4.655 | 4.875 (2 PLCS.) | 0.250\P(4 PLCS.) | 2.000\P(2 PLCS.) | 0.105\P(2 PLCS.) | dia 0.188\P(2 PLCS.) | 2.280 | 2.500\P(2 PLCS.) | 3.254 | 1.157 | 1.372 | POLYCASE
User.27: BOARD NO: 3H0009 | BOARD NAME: | CUSTOMER NAME: | TMDSSK3358 | REV: | 1.2 A | TEXAS INSTRUMENTS | DESCRIPTION: | DATE: | 05-31-2012 | SH | OF
User.28: L1_TOP | L3_SIG1 | L6_SIG2 | L8_BOTTOM | LAYERS | in mils | TRACE | WIDTH | 5.5 | 5.0 | SINGLE-ENDED | +/-10% | TARGET | Ohms | 50 | EDGE-COUPLED DIFFERENTIAL | SPACE | 90 | 4.75 | 4.0 | 6.5 | 100
User.29: SILKSCREEN TOP
User.30: SILKSCREEN BOTTOM | 2
User.35: 11. DESIGN HAS INTENTIONAL SHORTS AT SENSE RESISTORS AS SHOWN IN IPC356 NETLIST. | 9. ALL VIAS TO HAVE SOLDERMASK. | PROCESS NOTES: | 2. APPLY LPI SOLDERMASK OVER BARE COPPER (SMOBC), | COLOR: PURPLE SOLDERMASK SHALL | CONFORM TO IPC-SM-840, CLASS H. CURRENT REV. | 3. SOLDERMASK ARTWORK HAS ZERO (0) OVERSIZED PADS. | FABRICATION VENDOR IS ALLOWED TO ADJUST THE COMPONENT | SOLDERMASK PADS TO MEET THEIR TOOLING REQUIREMENTS. | 4. APPLY LPI SILKSCREEN OR EQUIVALENT PER THE ARTWORK. | COLOR: WHITE. | 1. PLATE ALL EXPOSED AREAS WITH ELECTROLESS | IMMERSION GOLD, NICKEL 150 MICROINCHES THK MIN | GOLD 5-15 MICROINCHES THK MIN. | FAB NOTES: | 1. ALL DIMENSIONS ARE IN INCHES, UNLESS | OTHERWISE NOTED. | 2. THE PWB SHALL BE FABRICATED TO IPC-6012, | CLASS 2 AND WORKMANSHIP SHALL CONFORM TO | IPC-A-600, CLASS 2. CURRENT REVISIONS. | 3. BOARD MATERIAL SHALL BE 180 Tg/350 Td ISOLA FR-408 HR | OR EQUIVALENT, RoHS COMPLIANT AND LEAD FREE | ASSEMBLY CAPABLE.  BOARD MATERIAL SHALL | MEET OR EXCEED IPC-4101B. COLOR: NATURAL. | 4. BOARD MATERIAL & CONSTRUCTION TO BE U.L. | APPROVED AND MARKED ON THE FINISHED BOARD. | 5. MINIMUM COPPER WALL THICKNESS OF PLATED-THRU | HOLES TO BE .001 INCH, WITH A MINIMUM | ANNULAR RING OF .002 INCH. | 6. OVERALL BOARD THICKNESS TO BE .062 +/- 10% | AND APPLIES AFTER ALL LAMINATION AND PLATING | PROCESSES, MEASURED FROM COPPER TO COPPER. | 7. MAX. WARP & TWIST TO BE .0075 INCHES PER INCH. | 8. BOARD MUST BE ELECTRICALLY TESTED USING | SUPPLIED IPC-D-356 NETLIST. | DRILL DRAWING | 1 | NOTE : | IMPEDANCE REQUIREMENT :- THIS DESIGN MAY NOT CONTAIN ALL THE FEATURES | LISTED IN THE ABOVE TABLE
User.36: Board edge | Board thickness | 0.063" | 30degree Min | 60degree Max | 0.014"+0.004"/-0.002"WEB | V-GROOVE WEB THICKNESS:
User.37: 4xR0.131 | 2x2.000 | 0.119 | 0.398 | 2.400 | 2.374 | 2.119 | 0 | 0.406 | 3.505 | 3.529 | 3.946 | 3.970 | 2x4.375 | 4.494 | 4.851
User.38: FIGURE | SIZE | 8.0 | 10.0 | 35.0 | 36.0 | 40.0 | 62.0 | 90.0 | 91.0 | 120.0 | 125.0 | 140.0 | 67.0 | DRILL CHART: TOP to BOTTOM | ALL UNITS ARE IN MILS | TOLERANCE | +3.0/-3.0 | +2.0/-2.0 | PLATED | NON-PLATED | QTY | 342 | 1519 | 20 | 4 | 22 | 2 | 1
